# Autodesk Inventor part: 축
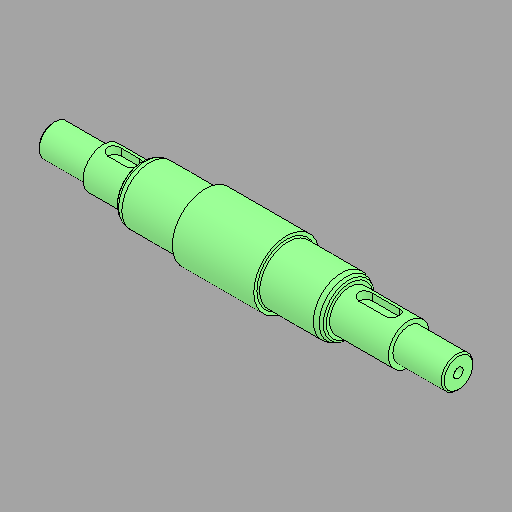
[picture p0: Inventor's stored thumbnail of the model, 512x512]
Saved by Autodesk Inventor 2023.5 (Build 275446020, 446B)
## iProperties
Created: 2025-07
Part Number: 축
Material: 강철, 탄소
Document SubType Name: Modeling
Designer: 1강의실14
Density: 7.85 g/cm^3
Appearance: 기본값
Author: jhkim
Sending System: Autodesk Inventor 2026
Preprocessor: ST-DEVELOPER v20.1
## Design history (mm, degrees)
feature "솔리드1"
node "솔리드2"
